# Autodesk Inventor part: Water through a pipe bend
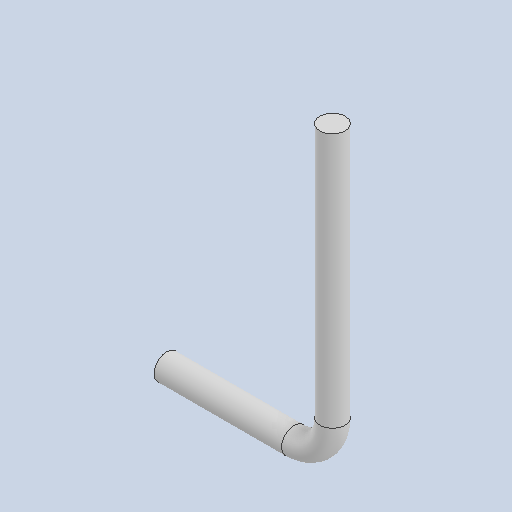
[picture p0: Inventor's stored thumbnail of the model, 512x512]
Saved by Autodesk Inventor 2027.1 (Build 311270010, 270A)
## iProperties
Created: 2026-10
Part Number: Water through a pipe bend
Material: Generic
Document SubType Name: Modeling
Designer: niels
Density: 1 g/cm^3
Appearance: Default
Author: niels
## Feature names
1. Sweep1
## Parameters: d1 = 0, d2 = 0
